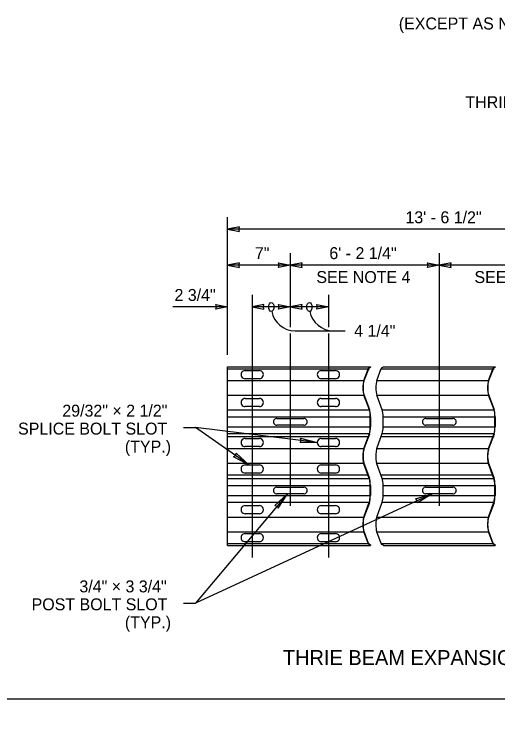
# Model space of a CAD drawing. Extents: x 36116 to 262144, y 33986 to 262144.
# Drawn here: x 100691 to 101339, y 99960 to 100916 of the extents above; entities that cross this region are included whole.
import ezdxf

# ---------------------------------------------------------------- set-up
doc = ezdxf.new("R2010")
doc.units = 0
for name, color, linetype in [('Level 1', 7, 'Continuous'), ('Level 10', 7, 'Continuous'), ('Level 15', 7, 'Continuous'), ('Level 2', 7, 'Continuous'), ('Level 20', 7, 'Continuous'), ('Level 27', 7, 'Continuous'), ('Level 5', 7, 'Continuous')]:
    doc.layers.add(name, color=color, linetype=linetype)

msp = doc.modelspace()

# ---------------------------------------------------------------- linework, layer by layer
at = {"layer": 'Level 1'}
msp.add_lwpolyline([(99862, 99999.5), (103151, 99999.5), (103151, 102075.5), (99862, 102075.5)], close=True, dxfattribs=at)
at = {"layer": 'Level 15'}
for p, q in [((100977.04507516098, 100460.3293208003), (100977.04507516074, 100644.32932080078)), ((101559.49945695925, 100628.3293208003), (100977.04507516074, 100628.3293208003)), ((101061.0450605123, 100596.3293208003), (101061.0450605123, 100497.09423488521)), ((101260.5955992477, 100596.3293208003), (101260.5955992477, 100258.10834028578)), ((101061.0450605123, 100580.3293208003), (100977.04507516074, 100580.3293208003)), ((101260.5955992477, 100580.3293208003), (101061.0450605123, 100580.3293208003)), ((101484.49943149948, 100580.3293208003), (101260.5955992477, 100580.3293208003)), ((101010.04507516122, 100540.3293208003), (101010.04507516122, 100188.82699784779)), ((101112.04507516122, 100540.3293208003), (101112.04507516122, 100497.09423138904)), ((100977.04507516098, 100524.3293208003), (100903.67617876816, 100524.3293208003)), ((101061.0450605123, 100524.3293208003), (101010.04507516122, 100524.3293208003)), ((101112.04507516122, 100524.3293208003), (101061.0450605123, 100524.3293208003)), ((101061.0450605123, 100488.92098979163), (101061.0450605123, 100258.10834028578)), ((101067.54506783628, 100492.32932079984), (101118.54506783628, 100492.32932079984)), ((101112.04507516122, 100488.92098710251), (101112.04507516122, 100188.82699784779)), ((101118.54506783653, 100492.32932079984), (101134.54506783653, 100492.32932079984)), ((100918.00939283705, 100362.7654800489), (100934.00939283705, 100362.7654800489)), ((101005.54938813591, 100312.77401791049), (100934.0093928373, 100362.7654800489)), ((101097.04507516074, 100342.76530554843), (100934.00939283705, 100362.7654800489)), ((101057.26217182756, 100274.1083402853), (100934.00939283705, 100127.4909773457)), ((101250.87043997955, 100274.10834028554), (100934.00939283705, 100127.4909773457)), ((100918.00939283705, 100127.4909773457), (100934.00939283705, 100127.4909773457))]:
    msp.add_line(p, q, dxfattribs=at)
for points in [[(100977.04507516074, 100628.3293208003), (100992.77007516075, 100625.24532080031), (100992.04207516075, 100628.3293208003), (100992.77007516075, 100631.4133208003)], [(100977.04507516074, 100580.3293208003), (100992.77007516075, 100577.24532080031), (100992.04207516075, 100580.3293208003), (100992.77007516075, 100583.4133208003)], [(101061.0450605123, 100580.3293208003), (101045.32006051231, 100577.24532080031), (101046.0480605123, 100580.3293208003), (101045.32006051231, 100583.4133208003)], [(101061.0450605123, 100580.3293208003), (101076.77006051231, 100577.24532080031), (101076.0420605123, 100580.3293208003), (101076.77006051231, 100583.4133208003)], [(101260.5955992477, 100580.3293208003), (101244.87059924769, 100577.24532080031), (101245.59859924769, 100580.3293208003), (101244.87059924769, 100583.4133208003)], [(101260.5955992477, 100580.3293208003), (101276.3205992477, 100577.24532080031), (101275.5925992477, 100580.3293208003), (101276.3205992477, 100583.4133208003)], [(100977.04507516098, 100524.3293208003), (100961.32007516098, 100521.24532080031), (100962.04807516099, 100524.3293208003), (100961.32007516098, 100527.4133208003)], [(101010.04507516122, 100524.3293208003), (101025.77007516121, 100521.24532080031), (101025.04207516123, 100524.3293208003), (101025.77007516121, 100527.4133208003)], [(101061.0450605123, 100524.3293208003), (101045.32006051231, 100521.24532080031), (101046.0480605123, 100524.3293208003), (101045.32006051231, 100527.4133208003)], [(101061.0450605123, 100524.3293208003), (101076.77006051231, 100521.24532080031), (101076.0420605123, 100524.3293208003), (101076.77006051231, 100527.4133208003)], [(101112.04507516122, 100524.3293208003), (101096.32007516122, 100521.24532080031), (101097.04807516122, 100524.3293208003), (101096.32007516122, 100527.4133208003)], [(101097.04507516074, 100342.76530554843), (101074.02247895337, 100342.58219388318), (101075.43407787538, 100345.41640444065), (101074.74839864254, 100348.50789566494)], [(101005.54938813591, 100312.77401791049), (100985.12671668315, 100323.40359724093), (100987.70211539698, 100325.24552081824), (100988.54549338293, 100328.29776385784)], [(101057.26217182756, 100274.1083402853), (101040.28725260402, 100258.55438312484), (101043.25167378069, 100257.44192274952), (101044.8564209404, 100254.71203986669)], [(101250.87043997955, 100274.10834028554), (101231.40546747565, 100261.81247466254), (101231.11031923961, 100264.96497343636), (101228.89751449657, 100267.23013770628)]]:
    msp.add_lwpolyline(points, close=True, dxfattribs=at)
for centre, start in [((101067.54506783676, 100524.32932079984), 190.66672520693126), ((101118.54506783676, 100524.32932079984), 190.66672520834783)]:
    msp.add_arc(centre, 32, start, 269.9999999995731, dxfattribs=at)
for centre in [(101035.545067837, 100524.3293208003), (101086.545067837, 100524.3293208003)]:
    msp.add_ellipse(centre, major_axis=(-9.648735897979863e-16, -5.999999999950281), ratio=0.5773502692, dxfattribs=at)
at = {"layer": 'Level 2'}
for p, q in [((100977.04507516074, 100204.82699784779), (100977.04507516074, 100444.3293208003)), ((100977.04507516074, 100444.3293208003), (101168.4903797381, 100444.3293208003)), ((101000.48257516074, 100439.121499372), (101019.60757516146, 100439.12149937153)), ((101102.48257516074, 100439.121499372), (101121.60757516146, 100439.12149937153)), ((101185.75682131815, 100444.3293208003), (101335.43440647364, 100444.3293208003)), ((101019.60757516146, 100428.24649937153), (101000.48257516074, 100428.246499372)), ((101121.60757516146, 100428.24649937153), (101102.48257516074, 100428.246499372)), ((101000.48257516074, 100401.76423480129), (101019.60757516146, 100401.76423480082)), ((101102.48257516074, 100401.76423480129), (101121.60757516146, 100401.76423480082)), ((101019.60757516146, 100390.88923480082), (101000.48257516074, 100390.88923480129)), ((101121.60757516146, 100390.88923480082), (101102.48257516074, 100390.88923480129)), ((101043.04507516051, 100375.0479490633), (101079.06131327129, 100375.04794906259)), ((101242.59561389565, 100375.0479490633), (101278.61185200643, 100375.04794906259)), ((101079.04504586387, 100366.04794906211), (101043.04507516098, 100366.0479490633)), ((101278.59558459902, 100366.04794906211), (101242.59561389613, 100366.0479490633)), ((101000.48257516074, 100348.2028055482), (101019.60757516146, 100348.20280554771)), ((101102.48257516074, 100348.2028055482), (101121.60757516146, 100348.20280554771)), ((101019.60757516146, 100337.32780554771), (101000.48257516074, 100337.3278055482)), ((101121.60757516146, 100337.32780554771), (101102.48257516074, 100337.3278055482)), ((101000.48257516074, 100312.77401791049), (101019.60757516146, 100312.77401791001)), ((101102.48257516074, 100312.77401791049), (101121.60757516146, 100312.77401791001)), ((101019.60757516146, 100301.89901791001), (101000.48257516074, 100301.89901791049)), ((101121.60757516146, 100301.89901791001), (101102.48257516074, 100301.89901791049)), ((101043.04507516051, 100283.10834028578), (101079.06131327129, 100283.10834028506)), ((101242.59561389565, 100283.10834028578), (101278.61185200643, 100283.10834028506)), ((101079.04504586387, 100274.10834028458), (101043.04507516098, 100274.10834028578)), ((101278.59558459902, 100274.10834028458), (101242.59561389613, 100274.10834028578)), ((101000.48257516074, 100258.26708384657), (101019.60757516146, 100258.26708384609)), ((101102.48257516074, 100258.26708384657), (101121.60757516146, 100258.26708384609)), ((101019.60757516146, 100247.39208384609), (101000.48257516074, 100247.39208384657)), ((101121.60757516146, 100247.39208384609), (101102.48257516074, 100247.39208384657)), ((101000.48257516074, 100220.81998148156), (101019.60757516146, 100220.81998148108)), ((101102.48257516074, 100220.81998148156), (101121.60757516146, 100220.81998148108)), ((101019.60757516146, 100209.94498148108), (101000.48257516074, 100209.94498148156)), ((101121.60757516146, 100209.94498148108), (101102.48257516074, 100209.94498148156)), ((100977.04507516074, 100204.82699784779), (101168.41189036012, 100204.82699784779)), ((101185.67833194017, 100204.82699784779), (101335.35591709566, 100204.82699784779))]:
    msp.add_line(p, q, dxfattribs=at)
for centre, radius, start, end in [((101000.48257516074, 100433.683999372), 5.4375, 89.99999999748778, 270.00000000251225), ((101019.60757516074, 100433.68399937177), 5.4375, 270, 90.00000000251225), ((101102.48257516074, 100433.683999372), 5.4375, 89.99999999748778, 270.00000000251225), ((101121.60757516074, 100433.68399937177), 5.4375, 270, 90.00000000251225), ((101000.48257516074, 100396.32673480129), 5.4375, 89.99999999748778, 270.00000000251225), ((101019.60757516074, 100396.32673480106), 5.4375, 270, 90.00000000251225), ((101102.48257516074, 100396.32673480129), 5.4375, 89.99999999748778, 270.00000000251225), ((101121.60757516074, 100396.32673480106), 5.4375, 270, 90.00000000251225), ((101043.04507516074, 100370.5479490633), 4.5, 89.9996269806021, 270), ((101079.04507516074, 100370.54797835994), 4.5, 269.9996269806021, 90.00000000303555), ((101242.5956138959, 100370.5479490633), 4.5, 89.9996269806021, 270), ((101278.5956138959, 100370.54797835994), 4.5, 269.9996269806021, 90.00000000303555), ((101000.48257516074, 100342.7653055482), 5.4375, 89.99999999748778, 270.00000000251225), ((101019.60757516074, 100342.76530554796), 5.4375, 270, 90.00000000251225), ((101102.48257516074, 100342.7653055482), 5.4375, 89.99999999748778, 270.00000000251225), ((101121.60757516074, 100342.76530554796), 5.4375, 270, 90.00000000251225), ((101000.48257516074, 100307.33651791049), 5.4375, 89.99999999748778, 270.00000000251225), ((101019.60757516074, 100307.33651791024), 5.4375, 270, 90.00000000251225), ((101102.48257516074, 100307.33651791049), 5.4375, 89.99999999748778, 270.00000000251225), ((101121.60757516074, 100307.33651791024), 5.4375, 270, 90.00000000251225), ((101043.04507516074, 100278.60834028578), 4.5, 89.9996269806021, 270), ((101079.04507516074, 100278.60836958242), 4.5, 269.9996269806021, 90.00000000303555), ((101242.5956138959, 100278.60834028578), 4.5, 89.9996269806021, 270), ((101278.5956138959, 100278.60836958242), 4.5, 269.9996269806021, 90.00000000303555), ((101000.48257516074, 100252.82958384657), 5.4375, 89.99999999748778, 270.00000000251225), ((101019.60757516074, 100252.82958384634), 5.4375, 270, 90.00000000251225), ((101102.48257516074, 100252.82958384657), 5.4375, 89.99999999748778, 270.00000000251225), ((101121.60757516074, 100252.82958384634), 5.4375, 270, 90.00000000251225), ((101000.48257516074, 100215.38248148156), 5.4375, 89.99999999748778, 270.00000000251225), ((101019.60757516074, 100215.38248148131), 5.4375, 270, 90.00000000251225), ((101102.48257516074, 100215.38248148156), 5.4375, 89.99999999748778, 270.00000000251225), ((101121.60757516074, 100215.38248148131), 5.4375, 270, 90.00000000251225)]:
    msp.add_arc(centre, radius, start, end, dxfattribs=at)
at = {"layer": 'Level 20'}
for points in [[(101159.5761479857, 100425.75758652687), (101165.23381621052, 100441.15158111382), (101165.45787802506, 100441.761232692)], [(101165.56882268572, 100441.15158117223), (101159.68726983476, 100425.14841712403)], [(101166.00072569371, 100442.63318128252), (101167.41307096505, 100443.59537706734), (101168.4903797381, 100444.3293208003), (101168.52387461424, 100443.5953771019), (101166.03422053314, 100441.89923731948)], [(101176.84258956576, 100425.75758652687), (101182.72431960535, 100441.761232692)], [(101183.267167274, 100442.63318128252), (101185.75682131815, 100444.3293208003)], [(101326.52017472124, 100425.75758652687), (101332.17784294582, 100441.15158111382), (101332.4019047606, 100441.761232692)], [(101332.51284942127, 100441.15158117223), (101326.6312965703, 100425.14841712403)], [(101332.94475242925, 100442.63318128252), (101334.35709770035, 100443.59537706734), (101335.43440647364, 100444.3293208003), (101335.46790134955, 100443.5953771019), (101332.97824726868, 100441.89923731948)], [(101166.87747575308, 100386.3945806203), (101159.57685830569, 100406.25888884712)], [(101159.68786223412, 100406.86837910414), (101166.98859792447, 100387.00374914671)], [(101184.14391733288, 100386.3945806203), (101176.84329988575, 100406.25888884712)], [(101333.82150248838, 100386.3945806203), (101326.52088504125, 100406.25888884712)], [(101326.63188896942, 100406.86837910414), (101333.93262465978, 100387.00374914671)], [(101168.1046014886, 100363.83855054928), (101168.10460145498, 100370.5479637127), (101168.1046014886, 100377.25737695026)], [(101168.29749063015, 100377.25536001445), (101168.29749059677, 100370.5479637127), (101168.29749063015, 100363.8405674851)], [(101185.37104306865, 100363.83855054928), (101185.37104303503, 100370.5479637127), (101185.37104306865, 100377.25737695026)], [(101335.04862822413, 100363.83855054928), (101335.04862819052, 100370.5479637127), (101335.04862822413, 100377.25737695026)], [(101335.24151736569, 100377.25536001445), (101335.24151733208, 100370.5479637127), (101335.24151736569, 100363.8405674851)], [(101159.57685830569, 100334.83703865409), (101166.87747575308, 100354.70134687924)], [(101166.98859792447, 100354.09217835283), (101159.68786223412, 100334.22754839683)], [(101176.84329988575, 100334.83703865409), (101184.14391733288, 100354.70134687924)], [(101326.52088504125, 100334.83703865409), (101333.82150248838, 100354.70134687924)], [(101333.93262465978, 100354.09217835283), (101326.63188896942, 100334.22754839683)], [(101159.60937285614, 100314.92877032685), (101166.9101085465, 100295.06414036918)], [(101326.55339959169, 100314.92877032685), (101333.85413528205, 100295.06414036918)], [(101166.7989863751, 100294.45497184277), (101159.49836892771, 100314.3192800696)], [(101184.06542795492, 100294.45497184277), (101176.76481050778, 100314.3192800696)], [(101333.7430131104, 100294.45497184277), (101326.44239566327, 100314.3192800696)], [(101168.02611211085, 100271.89894177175), (101168.02611207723, 100278.60835493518), (101168.02611211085, 100285.31776817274)], [(101168.21900125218, 100285.31575123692), (101168.2190012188, 100278.60835493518), (101168.21900125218, 100271.90095870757)], [(101185.29255369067, 100271.89894177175), (101185.2925536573, 100278.60835493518), (101185.29255369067, 100285.31776817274)], [(101334.97013884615, 100271.89894177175), (101334.97013881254, 100278.60835493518), (101334.97013884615, 100285.31776817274)], [(101335.16302798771, 100285.31575123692), (101335.1630279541, 100278.60835493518), (101335.16302798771, 100271.90095870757)], [(101159.49836892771, 100242.89742987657), (101166.7989863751, 100262.76173810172)], [(101166.9101085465, 100262.15256957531), (101159.60937285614, 100242.28793961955)], [(101176.76481050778, 100242.89742987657), (101184.06542795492, 100262.76173810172)], [(101326.44239566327, 100242.89742987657), (101333.7430131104, 100262.76173810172)], [(101333.85413528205, 100262.15256957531), (101326.55339959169, 100242.28793961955)], [(101165.37938864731, 100207.39508602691), (101165.15532685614, 100208.0047375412), (101159.49765860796, 100223.39873219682)], [(101159.60878045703, 100224.00790159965), (101165.49033330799, 100208.00473754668)], [(101182.64583022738, 100207.39508602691), (101176.76410018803, 100223.39873219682)], [(101332.32341538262, 100207.39508602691), (101332.09935359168, 100208.0047375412), (101326.44168534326, 100223.39873219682)], [(101326.55280719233, 100224.00790159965), (101332.43436004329, 100208.00473754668)], [(101165.95573115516, 100207.2570813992), (101168.44538523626, 100205.56094227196), (101168.41189036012, 100204.82699784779), (101167.33458053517, 100205.56094232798), (101165.92223631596, 100206.52313743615)], [(101185.67833194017, 100204.82699784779), (101183.18867789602, 100206.52313743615)], [(101332.8997578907, 100207.2570813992), (101335.3894119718, 100205.56094227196), (101335.35591709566, 100204.82699784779), (101334.27860727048, 100205.56094232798), (101332.86626305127, 100206.52313743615)]]:
    msp.add_lwpolyline(points, dxfattribs=at)
for centre, major_axis, ratio, start_param, end_param in [((101166.2351895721, 100437.49557354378), (1.4778171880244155e-15, 5.216863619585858), 0.25881904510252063, 0.17453292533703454, 0.6134489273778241), ((101166.2351895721, 100437.49557354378), (1.26670044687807e-15, 4.4715973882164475), 0.25881904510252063, 0.174532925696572, 0.6135544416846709), ((101183.50163115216, 100437.49557354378), (1.4778171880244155e-15, 5.216863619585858), 0.25881904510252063, 0.17453292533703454, 0.6134489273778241), ((101333.17921630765, 100437.49557354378), (1.4778171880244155e-15, 5.216863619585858), 0.25881904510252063, 0.17453292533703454, 0.6134489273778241), ((101333.17921630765, 100437.49557354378), (1.26670044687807e-15, 4.4715973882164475), 0.25881904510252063, 0.174532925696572, 0.6135544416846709), ((101161.35348323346, 100416.00920404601), (3.3778678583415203e-15, -11.924259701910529), 0.2588190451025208, 3.7552885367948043, 5.669770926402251), ((101161.35348323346, 100416.00920404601), (3.1667511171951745e-15, -11.17899347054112), 0.25881904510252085, 3.75527230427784, 5.669756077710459), ((101178.61992481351, 100416.00920404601), (3.3778678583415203e-15, -11.924259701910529), 0.2588190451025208, 3.7552885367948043, 5.669770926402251), ((101328.29750996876, 100416.00920404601), (3.3778678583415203e-15, -11.924259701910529), 0.2588190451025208, 3.7552885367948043, 5.669770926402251), ((101328.29750996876, 100416.00920404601), (3.1667511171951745e-15, -11.17899347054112), 0.25881904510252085, 3.75527230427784, 5.669756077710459), ((101165.21126512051, 100377.25536001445), (3.1667511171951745e-15, -11.17899347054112), 0.25881904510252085, 1.5709767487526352, 2.527914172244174), ((101165.21126512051, 100377.25536001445), (3.3778678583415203e-15, -11.924259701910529), 0.2588190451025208, 1.5707963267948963, 2.527897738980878), ((101182.47770670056, 100377.25536001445), (3.1667511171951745e-15, -11.17899347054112), 0.25881904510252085, 1.5709767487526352, 2.527914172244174), ((101332.15529185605, 100377.25536001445), (3.1667511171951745e-15, -11.17899347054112), 0.25881904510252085, 1.5709767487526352, 2.527914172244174), ((101332.15529185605, 100377.25536001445), (3.3778678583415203e-15, -11.924259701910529), 0.2588190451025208, 1.5707963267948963, 2.527897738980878), ((101165.21126512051, 100363.8405674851), (3.1667511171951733e-15, 11.178993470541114), 0.25881904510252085, 3.755271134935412, 4.712208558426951), ((101165.21126512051, 100363.8405674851), (3.377867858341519e-15, 11.924259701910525), 0.2588190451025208, 3.755287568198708, 4.71238898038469), ((101182.47770670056, 100363.8405674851), (3.1667511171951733e-15, 11.178993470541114), 0.25881904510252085, 3.755271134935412, 4.712208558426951), ((101332.15529185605, 100363.8405674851), (3.1667511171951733e-15, 11.178993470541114), 0.25881904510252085, 3.755271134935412, 4.712208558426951), ((101332.15529185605, 100363.8405674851), (3.377867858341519e-15, 11.924259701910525), 0.2588190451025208, 3.755287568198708, 4.71238898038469), ((101161.35348323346, 100325.0867234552), (3.377867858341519e-15, 11.924259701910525), 0.2588190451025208, 0.6973078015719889, 1.3255545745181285), ((101161.35348323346, 100325.0867234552), (3.1667511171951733e-15, 11.178993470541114), 0.25881904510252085, 0.6134292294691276, 1.328524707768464), ((101161.35348323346, 100325.0867234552), (3.377867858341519e-15, 11.924259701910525), 0.2588190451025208, 0.6134143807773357, 0.6973078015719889), ((101178.61992481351, 100325.0867234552), (3.377867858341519e-15, 11.924259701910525), 0.2588190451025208, 0.6134143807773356, 1.3255545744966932), ((101328.29750996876, 100325.0867234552), (3.377867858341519e-15, 11.924259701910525), 0.2588190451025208, 0.6973078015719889, 1.3255545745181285), ((101328.29750996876, 100325.0867234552), (3.1667511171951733e-15, 11.178993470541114), 0.25881904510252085, 0.6134292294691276, 1.328524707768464), ((101328.29750996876, 100325.0867234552), (3.377867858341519e-15, 11.924259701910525), 0.2588190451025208, 0.6134143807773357, 0.6973078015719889), ((101161.27499385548, 100324.06959526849), (3.3778678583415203e-15, -11.924259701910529), 0.2588190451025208, 4.3781081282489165, 5.669770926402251), ((101161.27499385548, 100324.06959526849), (3.1667511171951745e-15, -11.17899347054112), 0.25881904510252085, 4.375137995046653, 5.669756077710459), ((101178.54143543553, 100324.06959526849), (3.3778678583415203e-15, -11.924259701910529), 0.2588190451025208, 4.378108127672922, 5.6697709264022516), ((101328.21902059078, 100324.06959526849), (3.3778678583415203e-15, -11.924259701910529), 0.2588190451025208, 4.3781081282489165, 5.669770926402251), ((101328.21902059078, 100324.06959526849), (3.1667511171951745e-15, -11.17899347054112), 0.25881904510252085, 4.375137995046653, 5.669756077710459), ((101165.13277574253, 100285.31575123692), (3.1667511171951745e-15, -11.17899347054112), 0.25881904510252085, 1.5709767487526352, 2.527914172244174), ((101165.13277574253, 100285.31575123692), (3.3778678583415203e-15, -11.924259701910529), 0.2588190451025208, 1.5707963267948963, 2.527897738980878), ((101182.39921732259, 100285.31575123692), (3.1667511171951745e-15, -11.17899347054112), 0.25881904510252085, 1.5709767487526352, 2.527914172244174), ((101332.07680247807, 100285.31575123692), (3.1667511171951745e-15, -11.17899347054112), 0.25881904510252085, 1.5709767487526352, 2.527914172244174), ((101332.07680247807, 100285.31575123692), (3.3778678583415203e-15, -11.924259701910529), 0.2588190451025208, 1.5707963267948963, 2.527897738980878), ((101165.13277574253, 100271.90095870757), (3.1667511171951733e-15, 11.178993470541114), 0.25881904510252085, 3.755271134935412, 4.712208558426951), ((101165.13277574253, 100271.90095870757), (3.377867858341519e-15, 11.924259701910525), 0.2588190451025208, 3.755287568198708, 4.71238898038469), ((101182.39921732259, 100271.90095870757), (3.1667511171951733e-15, 11.178993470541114), 0.25881904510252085, 3.755271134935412, 4.712208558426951), ((101332.07680247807, 100271.90095870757), (3.1667511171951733e-15, 11.178993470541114), 0.25881904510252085, 3.755271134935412, 4.712208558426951), ((101332.07680247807, 100271.90095870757), (3.377867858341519e-15, 11.924259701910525), 0.2588190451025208, 3.755287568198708, 4.71238898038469), ((101161.27499385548, 100233.14711467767), (3.377867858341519e-15, 11.924259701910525), 0.2588190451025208, 0.697307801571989, 2.5278967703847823), ((101161.27499385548, 100233.14711467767), (3.1667511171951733e-15, 11.178993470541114), 0.25881904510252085, 0.6134292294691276, 2.527913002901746), ((101161.27499385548, 100233.14711467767), (3.377867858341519e-15, 11.924259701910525), 0.2588190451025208, 0.6134143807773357, 0.6973078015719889), ((101178.54143543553, 100233.14711467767), (3.377867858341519e-15, 11.924259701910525), 0.2588190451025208, 0.6134143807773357, 2.5278967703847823), ((101328.21902059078, 100233.14711467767), (3.377867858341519e-15, 11.924259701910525), 0.2588190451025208, 0.697307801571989, 2.5278967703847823), ((101328.21902059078, 100233.14711467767), (3.1667511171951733e-15, 11.178993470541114), 0.25881904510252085, 0.6134292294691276, 2.527913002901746), ((101328.21902059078, 100233.14711467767), (3.377867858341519e-15, 11.924259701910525), 0.2588190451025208, 0.6134143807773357, 0.6973078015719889), ((101166.15670019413, 100211.66074517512), (1.4778171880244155e-15, -5.216863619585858), 0.2588190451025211, 5.669736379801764, 6.108652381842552), ((101166.15670019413, 100211.66074517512), (1.2667004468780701e-15, -4.471597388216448), 0.2588190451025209, 5.6696308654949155, 6.108652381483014), ((101183.42314177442, 100211.66074517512), (1.4778171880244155e-15, -5.216863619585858), 0.2588190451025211, 5.669736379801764, 6.108652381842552), ((101333.10072692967, 100211.66074517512), (1.4778171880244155e-15, -5.216863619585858), 0.2588190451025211, 5.669736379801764, 6.108652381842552), ((101333.10072692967, 100211.66074517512), (1.2667004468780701e-15, -4.471597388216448), 0.2588190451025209, 5.6696308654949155, 6.108652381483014)]:
    msp.add_ellipse(centre, major_axis=major_axis, ratio=ratio, start_param=start_param, end_param=end_param, dxfattribs=at)
at = {"layer": 'Level 27'}
for p, q in [((100977.12356453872, 100441.6104122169), (101167.1115296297, 100441.6104122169)), ((101183.26716741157, 100441.6104122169), (101334.05555636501, 100441.6104122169)), ((100977.12356453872, 100425.75758652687), (101159.9111544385, 100425.75758652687)), ((101176.84258956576, 100425.75758652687), (101326.8551811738, 100425.75758652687)), ((100977.12356453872, 100406.2588889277), (101159.91186472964, 100406.2588889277)), ((101176.84329985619, 100406.2588889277), (101326.8558914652, 100406.2588889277)), ((100977.12356453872, 100386.39458067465), (101167.19359962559, 100386.39458067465)), ((101184.14391731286, 100386.39458067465), (101334.1376263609, 100386.39458067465)), ((100977.12356453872, 100377.25737676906), (101168.29749058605, 100377.25737676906)), ((101185.37104306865, 100377.25737676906), (101335.24151732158, 100377.25737676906)), ((100977.12356453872, 100363.83855065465), (101168.29749058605, 100363.83855065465)), ((101185.37104306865, 100363.83855065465), (101335.24151732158, 100363.83855065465)), ((100977.12356453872, 100354.70134675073), (101167.1935996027, 100354.70134675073)), ((101184.14391728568, 100354.70134675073), (101334.13762633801, 100354.70134675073)), ((100977.04507516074, 100350.69357259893), (101165.73952747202, 100350.69357259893)), ((101183.18867803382, 100350.69357259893), (101333.97706698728, 100350.69357259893)), ((100977.12356453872, 100334.83703849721), (101159.91186470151, 100334.83703849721)), ((101176.84329982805, 100334.83703849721), (101326.85589143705, 100334.83703849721)), ((100977.12356453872, 100315.33834097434), (101159.4681645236, 100315.33834097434)), ((101176.84258956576, 100315.33834097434), (101326.8551811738, 100315.33834097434)), ((100977.12356453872, 100299.33469484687), (101165.3405756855, 100299.33469484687)), ((101182.72431958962, 100299.33469484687), (101332.83203821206, 100299.33469484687)), ((100977.04507516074, 100294.45497189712), (101167.11511024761, 100294.45497189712)), ((101184.06542793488, 100294.45497189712), (101334.05913698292, 100294.45497189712)), ((100977.04507516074, 100285.31776799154), (101168.21900120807, 100285.31776799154)), ((101185.29255369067, 100285.31776799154), (101335.1630279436, 100285.31776799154)), ((100977.04507516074, 100271.89894187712), (101168.21900120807, 100271.89894187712)), ((101185.29255369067, 100271.89894187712), (101335.1630279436, 100271.89894187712)), ((100977.04507516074, 100262.76173797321), (101167.11511022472, 100262.76173797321)), ((101184.06542790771, 100262.76173797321), (101334.05913696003, 100262.76173797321)), ((100977.04507516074, 100242.89742971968), (101159.49836892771, 100242.89742971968)), ((101176.76481045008, 100242.89742971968), (101326.77740205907, 100242.89742971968)), ((100977.04507516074, 100223.39873219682), (101159.83266506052, 100223.39873219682)), ((101176.76410018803, 100223.39873219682), (101326.77669179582, 100223.39873219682)), ((100977.04507516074, 100207.3662307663), (101167.03304077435, 100207.3662307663)), ((101183.18867814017, 100207.3662307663), (101333.97706750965, 100207.3662307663))]:
    msp.add_line(p, q, dxfattribs=at)
at = {"layer": 'Level 5'}
msp.add_spline([(102147.42561003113, 100634.58530193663), (102161.82185687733, 100639.43976296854), (102158.73667169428, 100645.42865185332), (102162.72926428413, 100648.51383703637), (102160.91444947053, 100653.23235555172), (102160.91444947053, 100653.23235555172), (102154.43828568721, 100663.62584576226)], degree=3, dxfattribs=at)

# ---------------------------------------------------------------- texts
at = {"layer": 'Level 10'}
for s, p in [('29/32" × 2 1/2"', (100755.65781204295, 100377.40647303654)), ('SPLICE BOLT SLOT', (100696.39999213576, 100353.40647103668)), (' (TYP.)', (100833.50157177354, 100329.40646903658)), (' 3/4" × 3 3/4"', (100772.59726728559, 100142.13197033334)), ('POST BOLT SLOT', (100714.53085377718, 100118.13196833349)), (' (TYP.)', (100833.50157177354, 100094.13196633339))]:
    msp.add_text(s, height=16.000002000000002, dxfattribs=at).set_placement(p)
at = {"layer": 'Level 20'}
for s, height, p in [('(EXCEPT AS NOTED)', 16.000002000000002, (101206.32791522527, 100895.83335888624)), ('THRIE BEAM INSTALLED AT FACE OF BRIDGE RAIL', 16.000002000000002, (101295.54134807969, 100790.45447317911)), ('13\' - 6 1/2"', 16.000002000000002, (101215.16679067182, 100636.32931980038)), ('7"', 16.000002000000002, (101013.59215417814, 100588.32931980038)), ('6\' - 2 1/4"', 16.000002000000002, (101113.30665206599, 100588.32931980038)), ('SEE NOTE 4', 16.000002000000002, (101095.92383739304, 100556.32931780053)), ('SEE NOTE 4', 16.000002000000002, (101307.65102288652, 100556.32931780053)), ('2 3/4"', 16.000002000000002, (100905.87033376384, 100532.32931980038)), ('4 1/4"', 16.000002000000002, (101146.54506783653, 100484.3293197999)), ('THRIE BEAM EXPANSION SECTION', 19.999997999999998, (101051.09781860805, 100044.82699884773))]:
    msp.add_text(s, height=height, dxfattribs=at).set_placement(p)

doc.saveas('drawing.dxf')
